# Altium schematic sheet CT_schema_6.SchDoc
size 287 x 160 mm
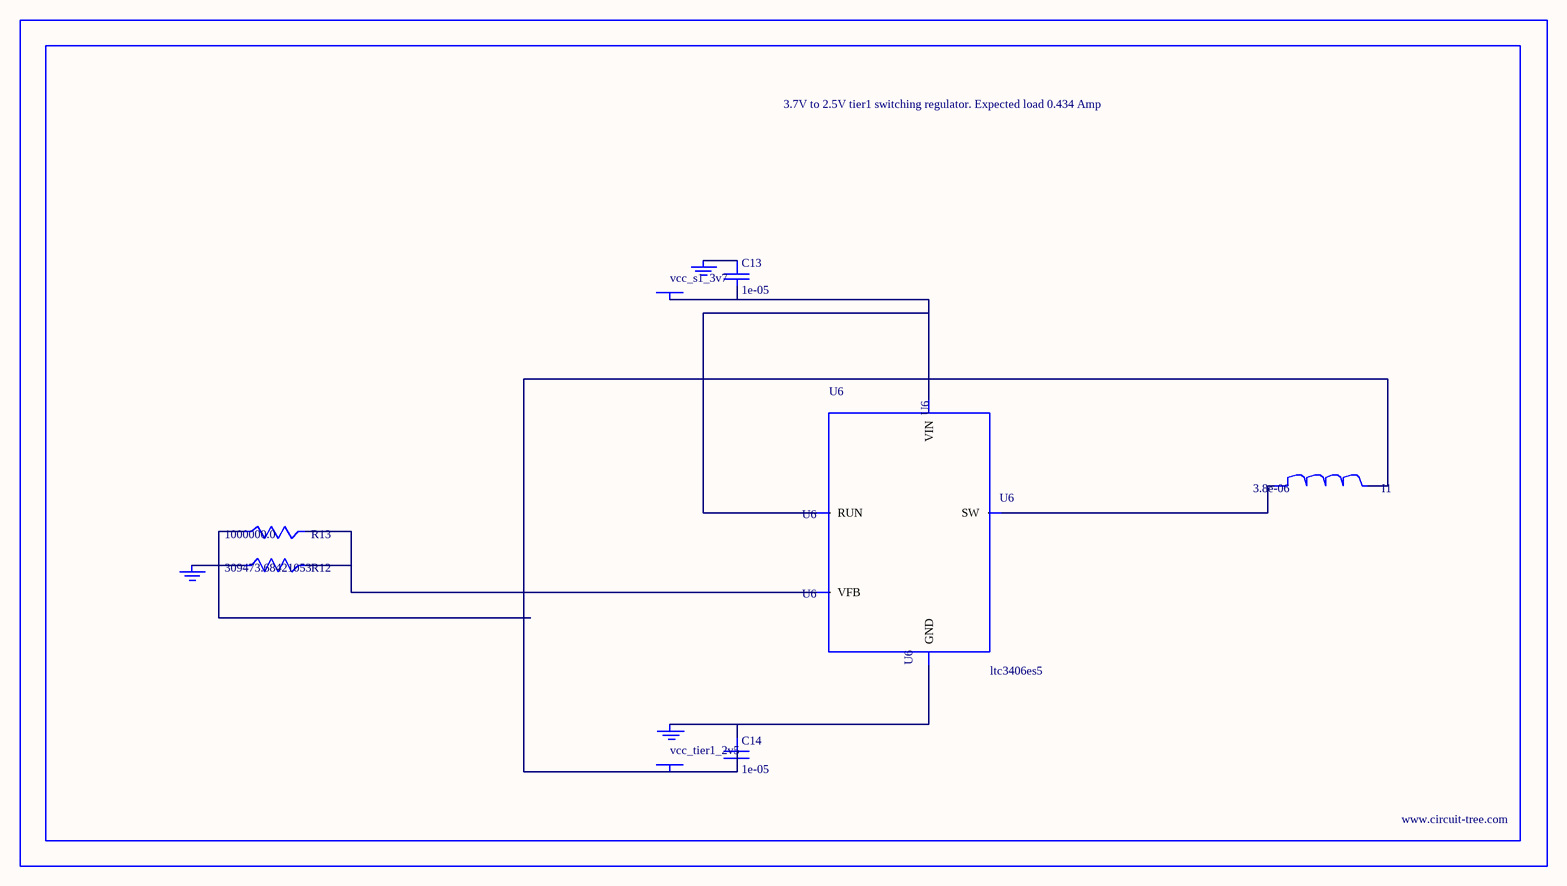
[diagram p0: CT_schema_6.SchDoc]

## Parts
BORDER5  (no value)
C13  1e-05  [C0805]
C14  1e-05  [C0805]
GND_INSTANCE_5_0  (no value)
GND_INSTANCE_5_1  (no value)
GND_INSTANCE_5_2  (no value)
I1  3.8e-06  [DR1040]
POWER_INSTANCE_5_0  vcc_tier1_2v5
POWER_INSTANCE_5_1  vcc_s1_3v7
R12  309473.68421053  [R0603]
R13  1000000.0  [R0603]
U6  ltc3406es5  [TSOT-23-5]

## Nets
NetC13_1: C13.1 GND_INSTANCE_5_1.0(GND)
NetC13_2: C13.2 POWER_INSTANCE_5_1.0(PWR) U6.1(RUN) U6.4(VIN)
NetC14_1: C14.1 GND_INSTANCE_5_0.0(GND) U6.2(GND)
NetC14_2: C14.2 I1.2 POWER_INSTANCE_5_0.0(PWR) R13.1
NetGND_INSTANCE_5_2_0: GND_INSTANCE_5_2.0(GND) R12.1
NetI1_1: I1.1 U6.3(SW)
NetR12_2: R12.2 R13.2 U6.5(VFB)

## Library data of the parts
BORDER5 = BORDER_PAGE5
C13 C14 = C0805C106K8RACTU
GND_INSTANCE_5_0-GND_INSTANCE_5_2 = GND
I1 = DR1040-3R8-R
POWER_INSTANCE_5_0 POWER_INSTANCE_5_1 = PWR
R12 = R12
R13 = RC0603JR-071ML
